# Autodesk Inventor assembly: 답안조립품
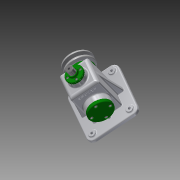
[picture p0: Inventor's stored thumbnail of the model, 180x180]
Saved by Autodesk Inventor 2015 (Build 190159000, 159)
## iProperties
Created: 2016-02
Part Number: 답안조립품
Document SubType Name: Assembly
Designer: Administrator
Author: Administrator
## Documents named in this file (19)
- C:\Users\Administrator\Desktop\460219V1006\답안조립품.iam
- C:\Users\Administrator\Desktop\460219V1006\V-벨트풀리.ipt
- C:\Users\Administrator\Desktop\460219V1006\고정핀.ipt
- C:\Users\Administrator\Desktop\460219V1006\뒤커버.ipt
- C:\Users\Administrator\Desktop\460219V1006\링크.ipt
- C:\Users\Administrator\Desktop\460219V1006\멈춤링 6 x 5.ipt
- C:\Users\Administrator\Desktop\460219V1006\멈춤링 15 x 1.ipt
- C:\Users\Administrator\Desktop\460219V1006\베어링 15 x 35 x 11.ipt
- C:\Users\Administrator\Desktop\460219V1006\본체.ipt
- C:\Users\Administrator\Desktop\460219V1006\볼트 M3 x 8.ipt
- C:\Users\Administrator\Desktop\460219V1006\볼트 M4 x 10.ipt
- C:\Users\Administrator\Desktop\460219V1006\볼트 M6 x 12.ipt
- C:\Users\Administrator\Desktop\460219V1006\상부부시.ipt
- C:\Users\Administrator\Desktop\460219V1006\슬라이드바.ipt
- C:\Users\Administrator\Desktop\460219V1006\앞커버.ipt
- C:\Users\Administrator\Desktop\460219V1006\오일실 15 25 7.ipt
- C:\Users\Administrator\Desktop\460219V1006\와셔.ipt
- C:\Users\Administrator\Desktop\460219V1006\키 5 x 5 x 14.ipt
- C:\Users\Administrator\Desktop\460219V1006\편심축.ipt
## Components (15 placed, 5 different names)
1. V-벨트풀리:1
2. 고정핀:1
3. ISO 4018 M6 x 12:1
4. ISO 4762 M4 x 10:1
5. ISO 4762 M4 x 10:3
6. ISO 4762 M4 x 10:4
7. ISO 4762 M4 x 10:5
8. ISO 4762 M3 x 8:1
9. ISO 4762 M3 x 8:2
10. ISO 4762 M3 x 8:3
11. ISO 4762 M3 x 8:4
12. ISO 4762 M4 x 10:2
13. ISO 4762 M4 x 10:6
14. ISO 4762 M4 x 10:7
15. ISO 4762 M4 x 10:8
